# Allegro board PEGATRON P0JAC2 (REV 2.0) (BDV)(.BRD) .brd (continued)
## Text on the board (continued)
Ref Des/Silkscreen Bottom: JP8205 | JP8301 | CON7305 | JP8206 | CON8001 | JP8207 | JP1602 | JP8203 | JP8204 | JP8102 | CON2101 | CON3301 | CON5101 | CON2003 | CON8902 | CON1102 | JP8305 | JP1601 | JP9000 | JP9001 | JP8302 | JP8201 | JP8303 | JP8202 | JP8304 | CON2002 | JP8402 | JP8800 | JP8900 | JP8901 | JP8306 | JP8307 | JP8100 | JP8101 | CON0700 | CON3800 | MAIN | AUX | BOT | 2nd
TOP: list("[Spacing] TOP" "8.Shape to Route Keepout" "0 MIL [DEFAULT]" "0 MIL" "0.00 MIL" "DRC ERROR CLASS/TOP" "[Shape] Route Keepout/Top ((-271.91 4409.28) (9.9 4687.15))" "[Top Shape] GND ((-679.11 -19.37) (3281.09 4854.01))" list(-261.910000 4409.280000) nil)@@@list("bobo_dong" "2014/01/13 20:45:47" nil "S0DCOA89102" "g1t-p0jac.11")@@@nil | list("[Spacing] TOP" "1.Shape to Route Keepin" "0 MIL [DEFAULT]" "0 MIL" "0.00 MIL" "DRC ERROR CLASS/TOP" "[Shape] Route Keepin/All ((-679.03 -19.38) (3281.17 4854.0))" "[Top Shape] GND ((-679.11 -19.37) (3281.09 4854.01))" list(-19.380000 -0.010000) nil)@@@list("bobo_dong" "2014/02/26 15:13:02" nil "S0DCOA89102" "g1t-p0jac.11")@@@list("vincent_kuo" "2014/02/26 12:02:35" nil "VINCENT_KUO-PC" "g1t-p0jac_byt-t.14") | list("[Spacing] TOP" "3.Shape to Route Keepout" "0 MIL [DEFAULT]" "0 MIL" "0.00 MIL" "DRC ERROR CLASS/TOP" "[Shape] Route Keepout/Top ((137.73 235.97) (253.73 351.97))" "[Top Shape] GND ((-679.11 -19.37) (3281.09 4854.01))" list(253.730000 293.970000) nil)@@@list("bobo_dong" "2014/01/13 20:45:44" nil "S0DCOA89102" "g1t-p0jac.11")@@@nil | list("[Spacing] TOP" "9.Thru Via to Route Keepout" "0 MIL [DEFAULT]" "0 MIL" "0.00 MIL" "DRC ERROR CLASS/TOP" "[Shape] Route Keepout/All ((-570.0 2225.0) (410.0 2765.0))" "[ThruVia] AU_HP_L (VIA20D10A32) (340.8 2717.6)" list(350.000000 2721.520000) nil)@@@list("bobo_dong" "2014/01/13 20:45:50" nil "S0DCOA89102" "g1t-p0jac.11")@@@nil | list("[Spacing] TOP" "7.Shape to Route Keepout" "0 MIL [DEFAULT]" "0 MIL" "0.00 MIL" "DRC ERROR CLASS/TOP" "[Shape] Route Keepout/Top ((351.73 4301.97) (467.73 4417.97))" "[Top Shape] GND ((-679.11 -19.37) (3281.09 4854.01))" list(467.730000 4359.970000) nil)@@@list("bobo_dong" "2014/01/13 20:45:47" nil "S0DCOA89102" "g1t-p0jac.11")@@@nil | list("[Spacing] TOP" "2.Shape to Route Keepout" "0 MIL [DEFAULT]" "0 MIL" "0.00 MIL" "DRC ERROR CLASS/TOP" "[Shape] Route Keepout/Top ((2572.73 10.97) (2688.73 126.97))" "[Top Shape] GND ((-679.11 -19.37) (3281.09 4854.01))" list(2688.730000 68.970000) nil)@@@list("bobo_dong" "2014/01/13 20:45:43" nil "S0DCOA89102" "g1t-p0jac.11")@@@nil | list("[Spacing] TOP" "6.Shape to Route Keepout" "0 MIL [DEFAULT]" "0 MIL" "0.00 MIL" "DRC ERROR CLASS/TOP" "[Shape] Route Keepout/Top ((2877.7 3995.9) (3056.0 4292.67))" "[Top Shape] GND ((-679.11 -19.37) (3281.09 4854.01))" list(2887.700000 3995.900000) nil)@@@list("bobo_dong" "2014/01/13 20:45:46" nil "S0DCOA89102" "g1t-p0jac.11")@@@nil | list("[Spacing] TOP" "70.Shape to Route Keepin" "0 MIL [DEFAULT]" "0 MIL" "0.00 MIL" "DRC ERROR CLASS/TOP" "[Shape] Route Keepin/All ((-679.11 -19.37) (3281.09 4854.01))" "[Top Shape] GND ((-679.11 -19.37) (3281.09 4854.01))" list(3104.240000 2379.050000) nil)@@@list("bobo_dong" "2014/01/13 20:45:44" nil "S0DCOA89102" "g1t-p0jac.11")@@@list("vincent_kuo" "2014/01/13 22:08:13" nil "VINCENT_KUO-PC" "g1t-p0jac_byt-t.11") | list("[Spacing] TOP" "1.Shape to Route Keepin" "0 MIL [DEFAULT]" "0 MIL" "0.00 MIL" "DRC ERROR CLASS/TOP" "[Shape] Route Keepin/All ((-679.11 -19.37) (3281.09 4854.01))" "[Top Shape] GND ((2887.7 4005.9) (3163.29 4282.67))" list(3143.290000 4196.060000) nil)@@@list("bobo_dong" "2014/01/13 20:45:41" nil "S0DCOA89102" "g1t-p0jac.11")@@@nil | list("[Spacing] TOP" "1.Shape to Route Keepin" "0 MIL [DEFAULT]" "0 MIL" "0.00 MIL" "DRC ERROR CLASS/TOP" "[Shape] Route Keepin/All ((-679.11 -19.37) (3281.09 4854.01))" "[Top Shape] GND ((-679.11 -19.37) (3281.09 4854.01))" list(3173.920000 1359.560000) nil)@@@list("bobo_dong" "2014/02/25 09:07:14" nil "s0dcoa89102" "g1t-p0jac.11")@@@nil | list("[Spacing] TOP" "1.Shape to Route Keepin" "0 MIL [DEFAULT]" "0 MIL" "0.00 MIL" "DRC ERROR CLASS/TOP" "[Shape] Route Keepin/All ((-679.11 -19.37) (3281.09 4854.01))" "[Top Shape] GND ((-679.11 -19.37) (3281.09 4854.01))" list(3189.060000 1979.830000) nil)@@@list("vincent_kuo" "2014/01/15 11:14:32" nil "VINCENT_KUO-PC" "g1t-p0jac_byt-t.12")@@@list("doris_chen" "2014/01/16 14:58:51" nil "JULIA_YU-PC1" "g1t-p0jac_byt-t.13-chk") | list("[Spacing] TOP" "5.Shape to Route Keepout" "0 MIL [DEFAULT]" "0 MIL" "0.00 MIL" "DRC ERROR CLASS/TOP" "[Shape] Route Keepout/All ((3220.45 3611.18) (3297.22 3837.56))" "[Top Shape] GND ((-679.11 -19.37) (3281.09 4854.01))" list(3281.090000 3837.560000) nil)@@@list("bobo_dong" "2014/01/13 20:45:45" nil "S0DCOA89102" "g1t-p0jac.11")@@@nil | list("[Spacing] TOP" "13.Line to Route Keepout" "0 MIL [DEFAULT]" "0 MIL" "0.00 MIL" "DRC ERROR CLASS/TOP" "[Shape] Route Keepout/Top ((-2910.16 444.47) (-2652.15 1060.2))" "[Line] 50_2.4G_5 ((-2888.16 774.8) (-2835.0 785.8))" list(-2843.860000 780.300000) nil)@@@list("lei_pang" "2013/05/31 11:02:39" nil "TERESA_YU-PC" "15t_ns_mb.100")@@@nil | list("[Spacing] TOP" "12.Line to Route Keepout" "0 MIL [DEFAULT]" "0 MIL" "0.00 MIL" "DRC ERROR CLASS/TOP" "[Shape] Route Keepout/Top ((-2910.16 444.47) (-2652.15 1060.2))" "[Line] 50_2.4G_5 ((-2846.0 774.8) (-2805.6 785.8))" list(-2833.600000 780.300000) nil)@@@list("lei_pang" "2013/05/31 11:02:38" nil "TERESA_YU-PC" "15t_ns_mb.100")@@@nil | list("[Spacing] TOP" "19.Line to Route Keepout" "0 MIL [DEFAULT]" "0 MIL" "0.00 MIL" "DRC ERROR CLASS/TOP" "[Shape] Route Keepout/Top ((-2910.16 444.47) (-2652.15 1060.2))" "[Line] 50_2.4G_0 ((-2768.35 466.47) (-2757.35 666.09))" list(-2762.850000 566.280000) nil)@@@list("lei_pang" "2013/05/31 11:02:45" nil "TERESA_YU-PC" "15t_ns_mb.100")@@@nil | list("[Spacing] TOP" "6.Line to Route Keepout" "0 MIL [DEFAULT]" "0 MIL" "0.00 MIL" "DRC ERROR CLASS/TOP" "[Shape] Route Keepout/Top ((-2910.16 444.47) (-2652.15 1060.2))" "[Line] 50_2.4G_4 ((-2783.6 774.8) (-2737.0 785.8))" list(-2760.300000 780.300000) nil)@@@list("lei_pang" "2013/05/31 11:02:31" nil "TERESA_YU-PC" "15t_ns_mb.100")@@@nil | list("[Spacing] TOP" "18.Line to Route Keepout" "0 MIL [DEFAULT]" "0 MIL" "0.00 MIL" "DRC ERROR CLASS/TOP" "[Shape] Route Keepout/Top ((-2910.16 444.47) (-2652.15 1060.2))" "[Arc] 50_2.4G_0 (-2737.839 660.59)" list(-2759.880000 672.400000) nil)@@@list("lei_pang" "2013/05/31 11:02:44" nil "TERESA_YU-PC" "15t_ns_mb.100")@@@nil | list("[Spacing] TOP" "7.Line to Route Keepout" "0 MIL [DEFAULT]" "0 MIL" "0.00 MIL" "DRC ERROR CLASS/TOP" "[Shape] Route Keepout/Top ((-2910.16 444.47) (-2652.15 1060.2))" "[Line] 50_2.4G_4 ((-2748.0 774.8) (-2707.15 785.8))" list(-2719.890000 780.300000) nil)@@@list("lei_pang" "2013/05/31 11:02:32" nil "TERESA_YU-PC" "15t_ns_mb.100")@@@nil | list("[Spacing] TOP" "17.Line to Route Keepout" "0 MIL [DEFAULT]" "0 MIL" "0.00 MIL" "DRC ERROR CLASS/TOP" "[Shape] Route Keepout/Top ((-2910.16 444.47) (-2652.15 1060.2))" "[Line] 50_2.4G_0 ((-2761.03 672.77) (-2681.47 752.33))" list(-2700.440000 733.360000) nil)@@@list("lei_pang" "2013/05/31 11:02:43" nil "TERESA_YU-PC" "15t_ns_mb.100")@@@nil | list("[Spacing] TOP" "16.Line to Route Keepout" "0 MIL [DEFAULT]" "0 MIL" "0.00 MIL" "DRC ERROR CLASS/TOP" "[Shape] Route Keepout/Top ((-2910.16 444.47) (-2652.15 1060.2))" "[Arc] 50_2.4G_0 (-2704.661 764.51)" list(-2682.620000 752.700000) nil)@@@list("lei_pang" "2013/05/31 11:02:42" nil "TERESA_YU-PC" "15t_ns_mb.100")@@@nil | list("[Spacing] TOP" "10.Line to Route Keepout" "0 MIL [DEFAULT]" "0 MIL" "0.00 MIL" "DRC ERROR CLASS/TOP" "[Shape] Route Keepout/Top ((-2910.16 444.47) (-2652.15 1060.2))" "[Line] 50_2.4G_3 ((-2685.15 996.32) (-2674.15 1038.2))" list(-2679.650000 1026.160000) nil)@@@list("lei_pang" "2013/05/31 11:02:35" nil "TERESA_YU-PC" "15t_ns_mb.100")@@@nil | list("[Spacing] TOP" "9.Line to Route Keepout" "0 MIL [DEFAULT]" "0 MIL" "0.00 MIL" "DRC ERROR CLASS/TOP" "[Shape] Route Keepout/Top ((-2910.16 444.47) (-2652.15 1060.2))" "[Line] 50_2.4G_2 ((-2685.15 932.82) (-2674.15 974.32))" list(-2679.650000 953.570000) nil)@@@list("lei_pang" "2013/05/31 11:02:34" nil "TERESA_YU-PC" "15t_ns_mb.100")@@@nil | list("[Spacing] TOP" "8.Line to Route Keepout" "0 MIL [DEFAULT]" "0 MIL" "0.00 MIL" "DRC ERROR CLASS/TOP" "[Shape] Route Keepout/Top ((-2910.16 444.47) (-2652.15 1060.2))" "[Line] 50_2.4G_2 ((-2685.15 899.42) (-2674.15 943.82))" list(-2679.650000 921.620000) nil)@@@list("lei_pang" "2013/05/31 11:02:33" nil "TERESA_YU-PC" "15t_ns_mb.100")@@@nil | list("[Spacing] TOP" "11.Line to Route Keepout" "0 MIL [DEFAULT]" "0 MIL" "0.00 MIL" "DRC ERROR CLASS/TOP" "[Shape] Route Keepout/Top ((-2910.16 444.47) (-2652.15 1060.2))" "[Line] 50_2.4G_1 ((-2685.15 836.62) (-2674.15 877.42))" list(-2679.650000 857.020000) nil)@@@list("lei_pang" "2013/05/31 11:02:36" nil "TERESA_YU-PC" "15t_ns_mb.100")@@@nil | list("[Spacing] TOP" "15.Line to Route Keepout" "0 MIL [DEFAULT]" "0 MIL" "0.00 MIL" "DRC ERROR CLASS/TOP" "[Shape] Route Keepout/Top ((-2910.16 444.47) (-2652.15 1060.2))" "[Line] 50_2.4G_0 ((-2685.15 774.8) (-2674.15 814.62))" list(-2679.650000 807.800000) nil)@@@list("lei_pang" "2013/05/31 11:02:41" nil "TERESA_YU-PC" "15t_ns_mb.100")@@@nil | list("[Spacing] TOP" "14.Line to Route Keepout" "0 MIL [DEFAULT]" "0 MIL" "0.00 MIL" "DRC ERROR CLASS/TOP" "[Shape] Route Keepout/Top ((-2910.16 444.47) (-2652.15 1060.2))" "[Line] 50_2.4G_0 ((-2685.15 759.01) (-2674.15 785.8))" list(-2679.650000 772.400000) nil)@@@list("lei_pang" "2013/05/31 11:02:40" nil "TERESA_YU-PC" "15t_ns_mb.100")@@@nil | list("[Spacing] TOP" "5.Shape to Route Keepout" "0 MIL [DEFAULT]" "0 MIL" "0.00 MIL" "DRC ERROR CLASS/TOP" "[Shape] Route Keepout/Top ((-2910.16 444.47) (-2652.15 1060.2))" "[Top Shape] 50_2.4G_3 ((-2684.45 891.05) (-2343.04 1048.55))" list(-2652.150000 1022.820000) nil)@@@list("lei_pang" "2013/05/31 11:02:30" nil "TERESA_YU-PC" "15t_ns_mb.100")@@@nil | list("[Spacing] TOP" "10.Thru Via to Route Keepin" "0 MIL [DEFAULT]" "1689.77 MIL" "-1689.77 MIL" "DRC ERROR CLASS/TOP" "[Shape] Route Keepin/All ((-2611.73 -1560.75) (2448.51 1842.01))" "[ThruVia] Dummy (VIA20D10A32) (-2910.0 -2405.0)" list(-2599.980000 -733.740000) nil)@@@list("sky_zheng" "2013/09/13 10:56:13" nil "RDD_704_PC" "g1t-oxygen.10")@@@list("andy_lien" "2013/09/13 12:14:47" nil "ANDY_LIEN-PC" "g1t-oxygen.10") | list("[Spacing] TOP" "9.Thru Via to Route Keepin" "0 MIL [DEFAULT]" "1713.38 MIL" "-1713.38 MIL" "DRC ERROR CLASS/TOP" "[Shape] Route Keepin/All ((-2611.73 -1560.75) (2448.51 1842.01))" "[ThruVia] Dummy (VIA20D10A32) (-2910.0 -2429.0)" list(-2599.940000 -733.750000) nil)@@@list("sky_zheng" "2013/09/13 10:56:14" nil "RDD_704_PC" "g1t-oxygen.10")@@@list("andy_lien" "2013/09/13 12:14:46" nil "ANDY_LIEN-PC" "g1t-oxygen.10") | list("[Spacing] TOP" "5.Shape to Route Keepout" "0 MIL [DEFAULT]" "0 MIL" "0.00 MIL" "DRC ERROR CLASS/TOP" "[Shape] Route Keepout/Top ((-2646.73 1357.01) (-2410.2 1826.97))" "[Top Shape] GND ((-2611.72 -1560.74) (2459.91 1842.0))" list(-2513.290000 1357.010000) nil)@@@list("sky_zheng" "2013/09/13 11:30:03" nil "RDD_704_PC" "g1t-oxygen.10")@@@list("andy_lien" "2013/09/13 12:14:37" nil "ANDY_LIEN-PC" "g1t-oxygen.10") | list("[Spacing] TOP" "4.Shape to Route Keepout" "0 MIL [DEFAULT]" "0 MIL" "0.00 MIL" "DRC ERROR CLASS/TOP" "[Shape] Route Keepout/Top ((-2636.95 -749.36) (-2419.97 -532.38))" "[Top Shape] GND ((-2611.72 -1560.74) (2459.91 1842.0))" list(-2419.970000 -640.370000) nil)@@@list("sky_zheng" "2013/09/13 11:30:02" nil "RDD_704_PC" "g1t-oxygen.10")@@@list("andy_lien" "2013/09/13 12:14:36" nil "ANDY_LIEN-PC" "g1t-oxygen.10") | list("[Spacing-SameNet] TOP" "31.Line to Line Same Net" "3 MIL [DEFAULT]" "0 MIL" "3.00 MIL" "DRC ERROR CLASS/TOP" "[Line] WLBT_3V3 ((-2299.11 137.5) (-2257.99 178.62))" "[Line] WLBT_3V3 ((-2290.11 78.8) (-2258.11 141.5))" list(-2273.990000 153.500000) nil)@@@list("lei_pang" "2013/05/31 11:03:01" nil "TERESA_YU-PC" "15t_ns_mb.100")@@@nil | list("[Spacing] TOP" "8.Line to Route Keepin" "0 MIL [DEFAULT]" "0 MIL" "0.00 MIL" "DRC ERROR CLASS/TOP" "[Shape] Route Keepin/All ((-2611.73 -1560.75) (2448.51 1842.01))" "[Line] PLUGDET_CONN_FB ((-1892.17 1479.03) (-1862.9 1508.3))" list(-1863.500000 1485.130000) nil)@@@list("sky_zheng" "2013/09/13 10:56:05" nil "RDD_704_PC" "g1t-oxygen.10")@@@list("andy_lien" "2013/09/13 12:14:44" nil "ANDY_LIEN-PC" "g1t-oxygen.10") | list("[Spacing] TOP" "7.SMD Pin to SMD Pin Same Net" "4 MIL [DEFAULT]" "OVERLAP" "" "DRC ERROR CLASS/TOP" "[SmdPin] +V1P0SX (<uTiL>cId1341<uTiL>.1) (-1655.0 -286.5)" "[SmdPin] +V1P0SX (<uTiL>cId885<uTiL>.2) (-1667.0 -285.0)" list(-1665.000000 -295.500000) nil)@@@list("sky_zheng" "2013/09/13 10:56:04" nil "RDD_704_PC" "g1t-oxygen.10")@@@list("andy_lien" "2013/09/13 12:14:43" nil "ANDY_LIEN-PC" "g1t-oxygen.10") | list("[Spacing] TOP" "20.Shape to Thru Via" "6 MIL [DEFAULT]" "2.09 MIL" "3.91 MIL" "DRC ERROR CLASS/TOP" "[ThruVia] 50_GPS_0 (VIA20D10A32) (-1601.0 768.0)" "[Top Shape] GND ((-3101.25 -1388.3) (1528.75 1237.87))" list(-1610.520000 771.050000) nil)@@@list("lei_pang" "2013/05/31 11:02:46" nil "TERESA_YU-PC" "15t_ns_mb.100")@@@nil | list("[Spacing] TOP" "1.Shape to Route Keepin" "0 MIL [DEFAULT]" "0 MIL" "0.00 MIL" "DRC ERROR CLASS/TOP" "[Shape] Route Keepin/All ((-2611.73 -1560.75) (2448.51 1842.01))" "[Top Shape] GND ((-1130.82 1739.05) (-1019.6 1813.85))" list(-1129.140000 1739.050000) nil)@@@list("sky_zheng" "2013/09/13 10:54:43" nil "RDD_704_PC" "g1t-oxygen.10")@@@list("andy_lien" "2013/09/13 12:14:27" nil "ANDY_LIEN-PC" "g1t-oxygen.10") | list("[Spacing] TOP" "6.Shape to Route Keepout" "0 MIL [DEFAULT]" "0 MIL" "0.00 MIL" "DRC ERROR CLASS/TOP" "[Shape] Route Keepout/Top ((2181.95 1490.8) (2398.93 1707.78))" "[Top Shape] GND ((-2611.72 -1560.74) (2459.91 1842.0))" list(2295.230000 1702.670000) nil)@@@list("sky_zheng" "2013/09/13 11:30:04" nil "RDD_704_PC" "g1t-oxygen.10")@@@list("andy_lien" "2013/09/13 12:14:38" nil "ANDY_LIEN-PC" "g1t-oxygen.10") | list("[Spacing] TOP" "2.Shape to Route Keepout" "0 MIL [DEFAULT]" "0 MIL" "0.00 MIL" "DRC ERROR CLASS/TOP" "[Shape] Route Keepout/Top ((2182.01 -965.83) (2483.51 -552.13))" "[Top Shape] GND ((-2611.72 -1560.74) (2459.91 1842.0))" list(2373.700000 -557.130000) nil)@@@list("sky_zheng" "2013/09/13 11:29:59" nil "RDD_704_PC" "g1t-oxygen.10")@@@list("andy_lien" "2013/09/13 12:14:29" nil "ANDY_LIEN-PC" "g1t-oxygen.10") | list("[Spacing] TOP" "3.Shape to Route Keepin" "0 MIL [DEFAULT]" "0 MIL" "0.00 MIL" "DRC ERROR CLASS/TOP" "[Shape] Route Keepin/All ((-2611.73 -1560.75) (2448.51 1842.01))" "[Top Shape] GND ((-2611.72 -1560.74) (2459.91 1842.0))" list(2418.390000 -961.140000) nil)@@@list("sky_zheng" "2013/09/13 11:30:00" nil "RDD_704_PC" "g1t-oxygen.10")@@@list("andy_lien" "2013/09/13 12:14:34" nil "ANDY_LIEN-PC" "g1t-oxygen.10") | list("[Spacing] TOP" "1.Shape to Route Keepout" "0 MIL [DEFAULT]" "0 MIL" "0.00 MIL" "DRC ERROR CLASS/TOP" "[Shape] Route Keepout/All ((-2636.73 -1585.75) (2473.51 1867.01))" "[Top Shape] GND ((-2611.72 -1560.74) (2459.91 1842.0))" list(2459.750000 -950.930000) nil)@@@list("sky_zheng" "2013/09/13 11:29:58" nil "RDD_704_PC" "g1t-oxygen.10")@@@nil
Ref Des/Silkscreen Top: H7906 | H7910 | J3101 | H7907 | CON0901 | H7903 | H7901 | H7911 | CON5201 | PCB MADE IN | P0JAC_BYT-T MAIN BOARD | REV:2.0 | 1.5/550MILS | 2014.03.20 | TOP | P0JAC_BYT-T MAIN BOARD REV:2.0 | 180 DEGREE | 0 DEGREE | 1st
L2-SIG: list("[Spacing] L2-SIG" "2.Shape to Route Keepin" "0 MIL [DEFAULT]" "0 MIL" "0.00 MIL" "DRC ERROR CLASS/L2-SIG" "[Shape] Route Keepin/All ((-679.03 -19.38) (3281.17 4854.0))" "[L2-Sig Shape] GND ((-679.11 -19.37) (3281.09 4854.01))" list(-19.380000 -0.010000) nil)@@@list("bobo_dong" "2014/02/26 15:13:03" nil "S0DCOA89102" "g1t-p0jac.11")@@@list("vincent_kuo" "2014/02/26 12:03:26" nil "VINCENT_KUO-PC" "g1t-p0jac_byt-t.14") | list("[Spacing] L2-SIG" "13.Thru Via to Route Keepout" "0 MIL [DEFAULT]" "0 MIL" "0.00 MIL" "DRC ERROR CLASS/L2-SIG" "[Shape] Route Keepout/All ((-570.0 2225.0) (410.0 2765.0))" "[ThruVia] AU_HP_L (VIA20D10A32) (340.8 2717.6)" list(350.000000 2721.520000) nil)@@@list("bobo_dong" "2014/01/13 20:46:38" nil "S0DCOA89102" "g1t-p0jac.11")@@@nil | list("[Spacing] L2-SIG" "2.Shape to Route Keepin" "0 MIL [DEFAULT]" "0 MIL" "0.00 MIL" "DRC ERROR CLASS/L2-SIG" "[Shape] Route Keepin/All ((-679.11 -19.37) (3281.09 4854.01))" "[L2-Sig Shape] GND ((-679.11 -19.37) (3281.09 4854.01))" list(3081.540000 2036.160000) nil)@@@list("bobo_dong" "2014/02/25 09:08:04" nil "s0dcoa89102" "g1t-p0jac.11")@@@nil | list("[Spacing] L2-SIG" "1.Shape to Route Keepin" "0 MIL [DEFAULT]" "0 MIL" "0.00 MIL" "DRC ERROR CLASS/L2-SIG" "[Shape] Route Keepin/All ((-679.11 -19.37) (3281.09 4854.01))" "[L2-Sig Shape] GND ((-679.11 -19.37) (3281.09 4854.01))" list(3104.240000 2379.050000) nil)@@@list("kelly_lv" "2014/01/14 09:49:14" nil "PC-0005358" "5k-castle.105")@@@list("vincent_kuo" "2014/01/13 22:05:46" nil "VINCENT_KUO-PC" "g1t-p0jac_byt-t.11") | list("[Spacing] L2-SIG" "12.Shape to Route Keepin" "0 MIL [DEFAULT]" "0 MIL" "0.00 MIL" "DRC ERROR CLASS/L2-SIG" "[Shape] Route Keepin/All ((-679.11 -19.37) (3281.09 4854.01))" "[L2-Sig Shape] GND ((-679.11 -19.37) (3281.09 4854.01))" list(3121.440000 1684.960000) nil)@@@list("bobo_dong" "2014/01/13 20:46:36" nil "S0DCOA89102" "g1t-p0jac.11")@@@nil | list("[Spacing] L2-SIG" "2.Shape to Route Keepin" "0 MIL [DEFAULT]" "0 MIL" "0.00 MIL" "DRC ERROR CLASS/L2-SIG" "[Shape] Route Keepin/All ((-679.11 -19.37) (3281.09 4854.01))" "[L2-Sig Shape] GND ((-679.11 -19.37) (3281.09 4854.01))" list(3173.920000 1359.560000) nil)@@@list("vincent_kuo" "2014/01/15 11:14:28" nil "VINCENT_KUO-PC" "g1t-p0jac_byt-t.12")@@@list("doris_chen" "2014/01/16 14:58:52" nil "JULIA_YU-PC1" "g1t-p0jac_byt-t.13-chk") | list("[Spacing] L2-SIG" "11.Shape to Route Keepout" "0 MIL [DEFAULT]" "0 MIL" "0.00 MIL" "DRC ERROR CLASS/L2-SIG" "[Shape] Route Keepout/All ((3220.45 3611.18) (3297.22 3837.56))" "[L2-Sig Shape] GND ((-679.11 -19.37) (3281.09 4854.01))" list(3281.090000 3837.560000) nil)@@@list("bobo_dong" "2014/01/13 20:46:35" nil "S0DCOA89102" "g1t-p0jac.11")@@@nil | list("[Spacing] L2-SIG" "4.Thru Via to Route Keepin" "0 MIL [DEFAULT]" "1689.77 MIL" "-1689.77 MIL" "DRC ERROR CLASS/L2-SIG" "[Shape] Route Keepin/All ((-2611.73 -1560.75) (2448.51 1842.01))" "[ThruVia] Dummy (VIA20D10A32) (-2910.0 -2405.0)" list(-2599.980000 -733.740000) nil)@@@list("sky_zheng" "2013/09/13 10:56:20" nil "RDD_704_PC" "g1t-oxygen.10")@@@list("andy_lien" "2013/09/13 12:14:52" nil "ANDY_LIEN-PC" "g1t-oxygen.10") | list("[Spacing] L2-SIG" "3.Thru Via to Route Keepin" "0 MIL [DEFAULT]" "1713.38 MIL" "-1713.38 MIL" "DRC ERROR CLASS/L2-SIG" "[Shape] Route Keepin/All ((-2611.73 -1560.75) (2448.51 1842.01))" "[ThruVia] Dummy (VIA20D10A32) (-2910.0 -2429.0)" list(-2599.940000 -733.750000) nil)@@@list("sky_zheng" "2013/09/13 10:56:21" nil "RDD_704_PC" "g1t-oxygen.10")@@@list("andy_lien" "2013/09/13 12:14:51" nil "ANDY_LIEN-PC" "g1t-oxygen.10") | list("[Spacing] L2-SIG" "1.Shape to Route Keepin" "0 MIL [DEFAULT]" "0 MIL" "0.00 MIL" "DRC ERROR CLASS/L2-SIG" "[Shape] Route Keepin/All ((-2611.73 -1560.75) (2448.51 1842.01))" "[L2-Sig Shape] GND ((-2199.6 1385.1) (-2005.01 1752.87))" list(-2195.600000 1424.680000) nil)@@@list("sky_zheng" "2013/09/13 10:56:19" nil "RDD_704_PC" "g1t-oxygen.10")@@@list("andy_lien" "2013/09/13 12:14:50" nil "ANDY_LIEN-PC" "g1t-oxygen.10") | list("[Spacing] L2-SIG" "19.Microvia to Route Keepin" "0 MIL [DEFAULT]" "46.46 MIL" "-46.46 MIL" "DRC ERROR CLASS/L2-SIG" "[Shape] Route Keepin/All ((-2611.73 -1560.75) (2448.51 1842.01))" "[B/BVia] Dummy (VIA10D4A24-L2-L3) (-1175.0 1805.0)" list(-1123.540000 1805.000000) nil)@@@list("sky_zheng" "2013/09/13 10:56:22" nil "RDD_704_PC" "g1t-oxygen.10")@@@nil | list("[Spacing] L2-SIG" "21.Microvia to Route Keepin" "0 MIL [DEFAULT]" "46.46 MIL" "-46.46 MIL" "DRC ERROR CLASS/L2-SIG" "[Shape] Route Keepin/All ((-2611.73 -1560.75) (2448.51 1842.01))" "[B/BVia] Dummy (VIA10D4A24-L2-L3) (-1175.0 1790.0)" list(-1123.540000 1790.000000) nil)@@@list("sky_zheng" "2013/09/13 10:56:24" nil "RDD_704_PC" "g1t-oxygen.10")@@@nil | list("[Spacing] L2-SIG" "20.Microvia to Route Keepin" "0 MIL [DEFAULT]" "46.46 MIL" "-46.46 MIL" "DRC ERROR CLASS/L2-SIG" "[Shape] Route Keepin/All ((-2611.73 -1560.75) (2448.51 1842.01))" "[B/BVia] Dummy (VIA10D4A24-L2-L3) (-1175.0 1775.0)" list(-1123.540000 1775.000000) nil)@@@list("sky_zheng" "2013/09/13 10:56:23" nil "RDD_704_PC" "g1t-oxygen.10")@@@nil | list("[Spacing] L2-SIG" "2.Shape to Route Keepin" "0 MIL [DEFAULT]" "0 MIL" "0.00 MIL" "DRC ERROR CLASS/L2-SIG" "[Shape] Route Keepin/All ((-2611.73 -1560.75) (2448.51 1842.01))" "[L2-Sig Shape] GND ((-2611.73 -1560.75) (2448.51 1842.01))" list(-13.300000 -778.660000) nil)@@@list("sky_zheng" "2013/09/13 10:56:18" nil "RDD_704_PC" "g1t-oxygen.10")@@@list("andy_lien" "2013/09/13 12:14:51" nil "ANDY_LIEN-PC" "g1t-oxygen.10") | list("[Spacing] L2-SIG" "13.Shape to Route Keepout" "0 MIL [DEFAULT]" "0 MIL" "0.00 MIL" "DRC ERROR CLASS/L2-SIG" "[Shape] Route Keepout/All ((190.63 -1315.47) (634.34 -438.7))" "[L2-Sig Shape] GND ((170.63 -1335.48) (654.34 -418.71))" list(190.630000 -495.210000) nil)@@@list("sky_zheng" "2013/09/13 10:56:15" nil "RDD_704_PC" "g1t-oxygen.10")@@@nil | list("[Spacing] L2-SIG" "14.Shape to Route Keepout" "0 MIL [DEFAULT]" "0 MIL" "0.00 MIL" "DRC ERROR CLASS/L2-SIG" "[Shape] Route Keepout/All ((184.14 -1363.31) (414.46 -390.87))" "[L2-Sig Shape] GND ((170.63 -1335.48) (654.34 -418.71))" list(390.830000 -418.710000) nil)@@@list("sky_zheng" "2013/09/13 10:56:15" nil "RDD_704_PC" "g1t-oxygen.10")@@@nil
L3-GND: list("[Spacing] L3-GND" "3.Shape to Route Keepin" "0 MIL [DEFAULT]" "0 MIL" "0.00 MIL" "DRC ERROR CLASS/L3-GND" "[Shape] Route Keepin/All ((-679.03 -19.38) (3281.17 4854.0))" "[L3-Gnd Shape] GND ((-679.11 -19.37) (3281.09 4854.01))" list(-19.380000 -0.010000) nil)@@@list("bobo_dong" "2014/02/26 15:13:05" nil "S0DCOA89102" "g1t-p0jac.11")@@@list("vincent_kuo" "2014/02/26 12:03:27" nil "VINCENT_KUO-PC" "g1t-p0jac_byt-t.14") | list("[Spacing] L3-GND" "16.Thru Via to Route Keepout" "0 MIL [DEFAULT]" "0 MIL" "0.00 MIL" "DRC ERROR CLASS/L3-GND" "[Shape] Route Keepout/All ((-570.0 2225.0) (410.0 2765.0))" "[ThruVia] AU_HP_L (VIA20D10A32) (340.8 2717.6)" list(350.000000 2721.520000) nil)@@@list("bobo_dong" "2014/01/13 20:46:43" nil "S0DCOA89102" "g1t-p0jac.11")@@@nil | list("[Spacing] L3-GND" "15.BB Via to Route Keepout" "0 MIL [DEFAULT]" "0 MIL" "0.00 MIL" "DRC ERROR CLASS/L3-GND" "[Shape] Route Keepout/All ((155.0 2225.0) (480.0 2457.5))" "[B/BVia] MICBIAS1 (VIA18D8A26-L3-L6) (413.0 2410.0)" list(420.000000 2415.660000) nil)@@@list("bobo_dong" "2014/01/13 20:46:41" nil "S0DCOA89102" "g1t-p0jac.11")@@@nil | list("[Spacing] L3-GND" "4.Shape to Route Keepin" "0 MIL [DEFAULT]" "0 MIL" "0.00 MIL" "DRC ERROR CLASS/L3-GND" "[Shape] Route Keepin/All ((-679.11 -19.37) (3281.09 4854.01))" "[L3-Gnd Shape] GND ((-679.11 -19.37) (3281.09 4854.01))" list(3104.240000 2379.050000) nil)@@@list("bobo_dong" "2014/01/13 20:46:39" nil "S0DCOA89102" "g1t-p0jac.11")@@@list("vincent_kuo" "2014/01/13 22:05:47" nil "VINCENT_KUO-PC" "g1t-p0jac_byt-t.11") | list("[Spacing] L3-GND" "3.Shape to Route Keepin" "0 MIL [DEFAULT]" "0 MIL" "0.00 MIL" "DRC ERROR CLASS/L3-GND" "[Shape] Route Keepin/All ((-679.11 -19.37) (3281.09 4854.01))" "[L3-Gnd Shape] GND ((-679.11 -19.37) (3281.09 4854.01))" list(3173.920000 1359.560000) nil)@@@list("bobo_dong" "2014/01/27 15:50:15" nil "s0dcoa89102" "g1t-p0jac.11")@@@nil | list("[Spacing] L3-GND" "3.Shape to Route Keepin" "0 MIL [DEFAULT]" "0 MIL" "0.00 MIL" "DRC ERROR CLASS/L3-GND" "[Shape] Route Keepin/All ((-679.11 -19.37) (3281.09 4854.01))" "[L3-Gnd Shape] GND ((-679.11 -19.37) (3281.09 4854.01))" list(3189.060000 1979.830000) nil)@@@list("bobo_dong" "2014/01/15 10:38:53" nil "S0DCOA89102" "g1t-p0jac.11")@@@list("doris_chen" "2014/01/16 14:58:53" nil "JULIA_YU-PC1" "g1t-p0jac_byt-t.13-chk") | list("[Spacing] L3-GND" "4.Thru Via to Route Keepin" "0 MIL [DEFAULT]" "1689.77 MIL" "-1689.77 MIL" "DRC ERROR CLASS/L3-GND" "[Shape] Route Keepin/All ((-2611.73 -1560.75) (2448.51 1842.01))" "[ThruVia] Dummy (VIA20D10A32) (-2910.0 -2405.0)" list(-2599.980000 -733.740000) nil)@@@list("sky_zheng" "2013/09/13 10:56:29" nil "RDD_704_PC" "g1t-oxygen.10")@@@list("andy_lien" "2013/09/13 12:14:56" nil "ANDY_LIEN-PC" "g1t-oxygen.10") | list("[Spacing] L3-GND" "3.Thru Via to Route Keepin" "0 MIL [DEFAULT]" "1713.38 MIL" "-1713.38 MIL" "DRC ERROR CLASS/L3-GND" "[Shape] Route Keepin/All ((-2611.73 -1560.75) (2448.51 1842.01))" "[ThruVia] Dummy (VIA20D10A32) (-2910.0 -2429.0)" list(-2599.940000 -733.750000) nil)@@@list("sky_zheng" "2013/09/13 10:56:30" nil "RDD_704_PC" "g1t-oxygen.10")@@@list("andy_lien" "2013/09/13 12:14:55" nil "ANDY_LIEN-PC" "g1t-oxygen.10") | list("[Spacing] L3-GND" "1.BB Via to Route Keepin" "0 MIL [DEFAULT]" "2040.83 MIL" "-2040.83 MIL" "DRC ERROR CLASS/L3-GND" "[Shape] Route Keepin/All ((-2611.73 -1560.75) (2448.51 1842.01))" "[B/BVia] Dummy (VIA18D8A26-L3-L6) (-2910.0 -2760.0)" list(-2599.530000 -733.810000) nil)@@@list("sky_zheng" "2013/09/13 10:56:31" nil "RDD_704_PC" "g1t-oxygen.10")@@@list("andy_lien" "2013/09/13 12:14:55" nil "ANDY_LIEN-PC" "g1t-oxygen.10") | list("[Spacing] L3-GND" "2.BB Via to Route Keepin" "0 MIL [DEFAULT]" "2062.58 MIL" "-2062.58 MIL" "DRC ERROR CLASS/L3-GND" "[Shape] Route Keepin/All ((-2611.73 -1560.75) (2448.51 1842.01))" "[B/BVia] Dummy (VIA18D8A26-L3-L6) (-2910.0 -2782.0)" list(-2599.510000 -733.820000) nil)@@@list("sky_zheng" "2013/09/13 10:56:32" nil "RDD_704_PC" "g1t-oxygen.10")@@@list("andy_lien" "2013/09/13 12:14:55" nil "ANDY_LIEN-PC" "g1t-oxygen.10") | list("[Spacing] L3-GND" "26.Microvia to Route Keepin" "0 MIL [DEFAULT]" "46.46 MIL" "-46.46 MIL" "DRC ERROR CLASS/L3-GND" "[Shape] Route Keepin/All ((-2611.73 -1560.75) (2448.51 1842.01))" "[B/BVia] Dummy (VIA10D4A24-L2-L3) (-1175.0 1805.0)" list(-1123.540000 1805.000000) nil)@@@list("sky_zheng" "2013/09/13 10:56:33" nil "RDD_704_PC" "g1t-oxygen.10")@@@nil | list("[Spacing] L3-GND" "28.Microvia to Route Keepin" "0 MIL [DEFAULT]" "46.46 MIL" "-46.46 MIL" "DRC ERROR CLASS/L3-GND" "[Shape] Route Keepin/All ((-2611.73 -1560.75) (2448.51 1842.01))" "[B/BVia] Dummy (VIA10D4A24-L2-L3) (-1175.0 1790.0)" list(-1123.540000 1790.000000) nil)@@@list("sky_zheng" "2013/09/13 10:56:53" nil "RDD_704_PC" "g1t-oxygen.10")@@@nil | list("[Spacing] L3-GND" "27.Microvia to Route Keepin" "0 MIL [DEFAULT]" "46.46 MIL" "-46.46 MIL" "DRC ERROR CLASS/L3-GND" "[Shape] Route Keepin/All ((-2611.73 -1560.75) (2448.51 1842.01))" "[B/BVia] Dummy (VIA10D4A24-L2-L3) (-1175.0 1775.0)" list(-1123.540000 1775.000000) nil)@@@list("sky_zheng" "2013/09/13 10:56:34" nil "RDD_704_PC" "g1t-oxygen.10")@@@nil
L4-SIG: list("[Spacing] L4-SIG" "4.Shape to Route Keepin" "0 MIL [DEFAULT]" "0 MIL" "0.00 MIL" "DRC ERROR CLASS/L4-SIG" "[Shape] Route Keepin/All ((-679.03 -19.38) (3281.17 4854.0))" "[L4-Sig Shape] GND ((-679.11 -19.37) (3281.09 4854.01))" list(-19.380000 -0.010000) nil)@@@list("bobo_dong" "2014/02/26 15:13:15" nil "S0DCOA89102" "g1t-p0jac.11")@@@list("vincent_kuo" "2014/02/26 12:03:29" nil "VINCENT_KUO-PC" "g1t-p0jac_byt-t.14") | list("[Spacing] L4-SIG" "25.Line to Route Keepout" "0 MIL [DEFAULT]" "0 MIL" "0.00 MIL" "DRC ERROR CLASS/L4-SIG" "[Shape] Route Keepout/All ((-570.0 2225.0) (410.0 2765.0))" "[Line] +V1P8S ((126.33 2508.0) (465.74 2518.0))" list(275.000000 2513.000000) nil)@@@list("bobo_dong" "2014/01/13 20:46:53" nil "S0DCOA89102" "g1t-p0jac.11")@@@nil | list("[Spacing] L4-SIG" "20.Thru Via to Route Keepout" "0 MIL [DEFAULT]" "0 MIL" "0.00 MIL" "DRC ERROR CLASS/L4-SIG" "[Shape] Route Keepout/All ((-570.0 2225.0) (410.0 2765.0))" "[ThruVia] AU_HP_L (VIA20D10A32) (340.8 2717.6)" list(350.000000 2721.520000) nil)@@@list("bobo_dong" "2014/01/13 20:46:48" nil "S0DCOA89102" "g1t-p0jac.11")@@@nil | list("[Spacing] L4-SIG" "1.Line to Route Keepout" "0 MIL [DEFAULT]" "0 MIL" "0.00 MIL" "DRC ERROR CLASS/L4-SIG" "[Shape] Route Keepout/All ((155.0 2225.0) (480.0 2457.5))" "[Line] GND ((195.8 2054.8) (386.0 2245.0))" list(366.000000 2225.000000) nil)@@@list("bobo_dong" "2014/01/13 21:08:35" nil "S0DCOA89102" "g1t-p0jac.11")@@@nil | list("[Spacing] L4-SIG" "24.Line to Route Keepout" "0 MIL [DEFAULT]" "0 MIL" "0.00 MIL" "DRC ERROR CLASS/L4-SIG" "[Shape] Route Keepout/All ((155.0 2225.0) (480.0 2457.5))" "[Line] GND ((195.8 2054.8) (391.2 2250.2))" list(366.000000 2225.000000) nil)@@@list("bobo_dong" "2014/01/13 20:46:52" nil "S0DCOA89102" "g1t-p0jac.11")@@@nil | list("[Spacing] L4-SIG" "2.Line to Route Keepout" "0 MIL [DEFAULT]" "0 MIL" "0.00 MIL" "DRC ERROR CLASS/L4-SIG" "[Shape] Route Keepout/All ((155.0 2225.0) (480.0 2457.5))" "[Line] GND ((366.0 2225.0) (452.2 2245.0))" list(409.100000 2235.000000) nil)@@@list("bobo_dong" "2014/01/13 21:08:36" nil "S0DCOA89102" "g1t-p0jac.11")@@@nil | list("[Spacing] L4-SIG" "22.Line to Route Keepout" "0 MIL [DEFAULT]" "0 MIL" "0.00 MIL" "DRC ERROR CLASS/L4-SIG" "[Shape] Route Keepout/All ((155.0 2225.0) (480.0 2457.5))" "[Line] GND ((371.2 2230.2) (457.4 2250.2))" list(414.300000 2240.200000) nil)@@@list("bobo_dong" "2014/01/13 20:46:50" nil "S0DCOA89102" "g1t-p0jac.11")@@@nil | list("[Spacing] L4-SIG" "19.BB Via to Route Keepout" "0 MIL [DEFAULT]" "0 MIL" "0.00 MIL" "DRC ERROR CLASS/L4-SIG" "[Shape] Route Keepout/All ((155.0 2225.0) (480.0 2457.5))" "[B/BVia] MICBIAS1 (VIA18D8A26-L3-L6) (413.0 2410.0)" list(420.000000 2415.660000) nil)@@@list("bobo_dong" "2014/01/13 20:46:47" nil "S0DCOA89102" "g1t-p0jac.11")@@@nil | list("[Spacing] L4-SIG" "21.Line to Route Keepout" "0 MIL [DEFAULT]" "0 MIL" "0.00 MIL" "DRC ERROR CLASS/L4-SIG" "[Shape] Route Keepout/All ((155.0 2225.0) (480.0 2457.5))" "[Line] GND ((437.4 2230.2) (475.23 2268.03))" list(452.200000 2245.000000) nil)@@@list("bobo_dong" "2014/01/13 20:46:50" nil "S0DCOA89102" "g1t-p0jac.11")@@@nil | list("[Spacing] L4-SIG" "3.Line to Route Keepout" "0 MIL [DEFAULT]" "0 MIL" "0.00 MIL" "DRC ERROR CLASS/L4-SIG" "[Shape] Route Keepout/All ((155.0 2225.0) (480.0 2457.5))" "[Line] GND ((432.2 2225.0) (475.23 2268.03))" list(452.200000 2245.000000) nil)@@@list("bobo_dong" "2014/01/13 21:08:37" nil "S0DCOA89102" "g1t-p0jac.11")@@@nil | list("[Spacing] L4-SIG" "23.Line to Route Keepout" "0 MIL [DEFAULT]" "0 MIL" "0.00 MIL" "DRC ERROR CLASS/L4-SIG" "[Shape] Route Keepout/All ((155.0 2225.0) (480.0 2457.5))" "[Line] GND ((455.23 2248.03) (475.23 2479.48))" list(465.230000 2378.910000) nil)@@@list("bobo_dong" "2014/01/13 20:46:51" nil "S0DCOA89102" "g1t-p0jac.11")@@@nil | list("[Spacing] L4-SIG" "3.Shape to Route Keepin" "0 MIL [DEFAULT]" "0 MIL" "0.00 MIL" "DRC ERROR CLASS/L4-SIG" "[Shape] Route Keepin/All ((-679.11 -19.37) (3281.09 4854.01))" "[L4-Sig Shape] GND ((-679.11 -19.37) (3281.09 4854.01))" list(3080.680000 2370.190000) nil)@@@list("bobo_dong" "2014/02/25 09:08:09" nil "s0dcoa89102" "g1t-p0jac.11")@@@list("vincent_kuo" "2014/01/13 22:05:48" nil "VINCENT_KUO-PC" "g1t-p0jac_byt-t.11") | list("[Spacing] L4-SIG" "4.Shape to Route Keepin" "0 MIL [DEFAULT]" "0 MIL" "0.00 MIL" "DRC ERROR CLASS/L4-SIG" "[Shape] Route Keepin/All ((-679.11 -19.37) (3281.09 4854.01))" "[L4-Sig Shape] GND ((-679.11 -19.37) (3281.09 4854.01))" list(3173.920000 1359.560000) nil)@@@list("vincent_kuo" "2014/01/15 11:14:29" nil "VINCENT_KUO-PC" "g1t-p0jac_byt-t.12")@@@list("doris_chen" "2014/01/16 14:58:55" nil "JULIA_YU-PC1" "g1t-p0jac_byt-t.13-chk") | list("[Spacing] L4-SIG" "17.Shape to Route Keepout" "0 MIL [DEFAULT]" "0 MIL" "0.00 MIL" "DRC ERROR CLASS/L4-SIG" "[Shape] Route Keepout/All ((3220.45 3611.18) (3297.22 3837.56))" "[L4-Sig Shape] GND ((-679.11 -19.37) (3281.09 4854.01))" list(3281.090000 3837.560000) nil)@@@list("bobo_dong" "2014/01/13 20:46:44" nil "S0DCOA89102" "g1t-p0jac.11")@@@nil | list("[Spacing] L4-SIG" "6.Thru Via to Route Keepin" "0 MIL [DEFAULT]" "1689.77 MIL" "-1689.77 MIL" "DRC ERROR CLASS/L4-SIG" "[Shape] Route Keepin/All ((-2611.73 -1560.75) (2448.51 1842.01))" "[ThruVia] Dummy (VIA20D10A32) (-2910.0 -2405.0)" list(-2599.980000 -733.740000) nil)@@@list("sky_zheng" "2013/09/13 10:56:58" nil "RDD_704_PC" "g1t-oxygen.10")@@@list("andy_lien" "2013/09/13 12:15:01" nil "ANDY_LIEN-PC" "g1t-oxygen.10") | list("[Spacing] L4-SIG" "5.Thru Via to Route Keepin" "0 MIL [DEFAULT]" "1713.38 MIL" "-1713.38 MIL" "DRC ERROR CLASS/L4-SIG" "[Shape] Route Keepin/All ((-2611.73 -1560.75) (2448.51 1842.01))" "[ThruVia] Dummy (VIA20D10A32) (-2910.0 -2429.0)" list(-2599.940000 -733.750000) nil)@@@list("sky_zheng" "2013/09/13 10:56:59" nil "RDD_704_PC" "g1t-oxygen.10")@@@list("andy_lien" "2013/09/13 12:15:00" nil "ANDY_LIEN-PC" "g1t-oxygen.10") | list("[Spacing] L4-SIG" "3.BB Via to Route Keepin" "0 MIL [DEFAULT]" "2040.83 MIL" "-2040.83 MIL" "DRC ERROR CLASS/L4-SIG" "[Shape] Route Keepin/All ((-2611.73 -1560.75) (2448.51 1842.01))" "[B/BVia] Dummy (VIA18D8A26-L3-L6) (-2910.0 -2760.0)" list(-2599.530000 -733.810000) nil)@@@list("sky_zheng" "2013/09/13 10:57:00" nil "RDD_704_PC" "g1t-oxygen.10")@@@list("andy_lien" "2013/09/13 12:14:59" nil "ANDY_LIEN-PC" "g1t-oxygen.10") | list("[Spacing] L4-SIG" "4.BB Via to Route Keepin" "0 MIL [DEFAULT]" "2062.58 MIL" "-2062.58 MIL" "DRC ERROR CLASS/L4-SIG" "[Shape] Route Keepin/All ((-2611.73 -1560.75) (2448.51 1842.01))" "[B/BVia] Dummy (VIA18D8A26-L3-L6) (-2910.0 -2782.0)" list(-2599.510000 -733.820000) nil)@@@list("sky_zheng" "2013/09/13 10:57:01" nil "RDD_704_PC" "g1t-oxygen.10")@@@list("andy_lien" "2013/09/13 12:15:00" nil "ANDY_LIEN-PC" "g1t-oxygen.10") | list("[Spacing] L4-SIG" "1.Shape to Route Keepin" "0 MIL [DEFAULT]" "0 MIL" "0.00 MIL" "DRC ERROR CLASS/L4-SIG" "[Shape] Route Keepin/All ((-2611.73 -1560.75) (2448.51 1842.01))" "[L4-Sig Shape] GND ((-2199.6 1385.1) (-2005.01 1752.87))" list(-2195.600000 1424.680000) nil)@@@list("sky_zheng" "2013/09/13 10:56:56" nil "RDD_704_PC" "g1t-oxygen.10")@@@list("andy_lien" "2013/09/13 12:14:58" nil "ANDY_LIEN-PC" "g1t-oxygen.10") | list("[Spacing] L4-SIG" "2.Shape to Route Keepin" "0 MIL [DEFAULT]" "0 MIL" "0.00 MIL" "DRC ERROR CLASS/L4-SIG" "[Shape] Route Keepin/All ((-2611.73 -1560.75) (2448.51 1842.01))" "[L4-Sig Shape] GND ((-2611.73 -1560.75) (2448.51 1842.01))" list(-13.300000 -778.660000) nil)@@@list("sky_zheng" "2013/09/13 10:56:57" nil "RDD_704_PC" "g1t-oxygen.10")@@@list("andy_lien" "2013/09/13 12:14:59" nil "ANDY_LIEN-PC" "g1t-oxygen.10") | list("[Spacing] L4-SIG" "29.Shape to Route Keepout" "0 MIL [DEFAULT]" "0 MIL" "0.00 MIL" "DRC ERROR CLASS/L4-SIG" "[Shape] Route Keepout/All ((190.63 -1315.47) (634.34 -438.7))" "[L4-Sig Shape] GND ((170.63 -1335.48) (654.34 -418.71))" list(190.630000 -495.210000) nil)@@@list("sky_zheng" "2013/09/13 10:56:55" nil "RDD_704_PC" "g1t-oxygen.10")@@@nil | list("[Spacing] L4-SIG" "30.Shape to Route Keepout" "0 MIL [DEFAULT]" "0 MIL" "0.00 MIL" "DRC ERROR CLASS/L4-SIG" "[Shape] Route Keepout/All ((184.14 -1363.31) (414.46 -390.87))" "[L4-Sig Shape] GND ((170.63 -1335.48) (654.34 -418.71))" list(390.830000 -418.710000) nil)@@@list("sky_zheng" "2013/09/13 10:56:55" nil "RDD_704_PC" "g1t-oxygen.10")@@@nil
L5-SIG: list("[Spacing] L5-SIG" "5.Shape to Route Keepin" "0 MIL [DEFAULT]" "0 MIL" "0.00 MIL" "DRC ERROR CLASS/L5-SIG" "[Shape] Route Keepin/All ((-679.03 -19.38) (3281.17 4854.0))" "[L5-Sig Shape] GND ((-679.11 -19.37) (3281.09 4854.01))" list(-19.380000 -0.010000) nil)@@@list("bobo_dong" "2014/02/26 15:13:17" nil "S0DCOA89102" "g1t-p0jac.11")@@@list("vincent_kuo" "2014/02/26 12:03:44" nil "VINCENT_KUO-PC" "g1t-p0jac_byt-t.14") | list("[Spacing] L5-SIG" "30.Line to Route Keepout" "0 MIL [DEFAULT]" "0 MIL" "0.00 MIL" "DRC ERROR CLASS/L5-SIG" "[Shape] Route Keepout/All ((-570.0 2225.0) (410.0 2765.0))" "[Line] AU_HP_JD# ((10.6 2449.6) (91.0 2530.0))" list(30.600000 2510.000000) nil)@@@list("bobo_dong" "2014/01/13 20:46:59" nil "S0DCOA89102" "g1t-p0jac.11")@@@nil | list("[Spacing] L5-SIG" "32.Line to Route Keepout" "0 MIL [DEFAULT]" "0 MIL" "0.00 MIL" "DRC ERROR CLASS/L5-SIG" "[Shape] Route Keepout/All ((-570.0 2225.0) (410.0 2765.0))" "[Line] AU_HP_L ((338.8 2690.08) (342.8 2719.6))" list(340.800000 2692.560000) nil)@@@list("bobo_dong" "2014/01/13 20:47:01" nil "S0DCOA89102" "g1t-p0jac.11")@@@nil | list("[Spacing] L5-SIG" "31.Line to Route Keepout" "0 MIL [DEFAULT]" "0 MIL" "0.00 MIL" "DRC ERROR CLASS/L5-SIG" "[Shape] Route Keepout/All ((-570.0 2225.0) (410.0 2765.0))" "[Line] AU_HP_L ((314.72 2666.0) (342.8 2694.08))" list(340.800000 2692.080000) nil)@@@list("bobo_dong" "2014/01/13 20:47:00" nil "S0DCOA89102" "g1t-p0jac.11")@@@nil | list("[Spacing] L5-SIG" "33.Thru Via to Route Keepout" "0 MIL [DEFAULT]" "0 MIL" "0.00 MIL" "DRC ERROR CLASS/L5-SIG" "[Shape] Route Keepout/All ((-570.0 2225.0) (410.0 2765.0))" "[ThruVia] AU_HP_L (VIA20D10A32) (340.8 2717.6)" list(350.000000 2721.520000) nil)@@@list("bobo_dong" "2014/01/13 20:47:02" nil "S0DCOA89102" "g1t-p0jac.11")@@@nil | list("[Spacing] L5-SIG" "29.BB Via to Route Keepout" "0 MIL [DEFAULT]" "0 MIL" "0.00 MIL" "DRC ERROR CLASS/L5-SIG" "[Shape] Route Keepout/All ((155.0 2225.0) (480.0 2457.5))" "[B/BVia] MICBIAS1 (VIA18D8A26-L3-L6) (413.0 2410.0)" list(420.000000 2415.660000) nil)@@@list("bobo_dong" "2014/01/13 20:46:57" nil "S0DCOA89102" "g1t-p0jac.11")@@@nil | list("[Spacing] L5-SIG" "26.Shape to Route Keepout" "0 MIL [DEFAULT]" "0 MIL" "0.00 MIL" "DRC ERROR CLASS/L5-SIG" "[Shape] Route Keepout/All ((3056.9 2031.81) (3317.13 2375.11))" "[L5-Sig Shape] GND ((-679.11 -19.37) (3281.09 4854.01))" list(3080.340000 2369.890000) nil)@@@list("bobo_dong" "2014/01/13 20:46:54" nil "S0DCOA89102" "g1t-p0jac.11")@@@nil | list("[Spacing] L5-SIG" "4.Shape to Route Keepin" "0 MIL [DEFAULT]" "0 MIL" "0.00 MIL" "DRC ERROR CLASS/L5-SIG" "[Shape] Route Keepin/All ((-679.11 -19.37) (3281.09 4854.01))" "[L5-Sig Shape] GND ((-679.11 -19.37) (3281.09 4854.01))" list(3173.940000 1359.560000) nil)@@@list("bobo_dong" "2014/02/25 09:08:13" nil "s0dcoa89102" "g1t-p0jac.11")@@@list("vincent_kuo" "2014/01/13 22:06:21" nil "VINCENT_KUO-PC" "g1t-p0jac_byt-t.11") | list("[Spacing] L5-SIG" "5.Shape to Route Keepin" "0 MIL [DEFAULT]" "0 MIL" "0.00 MIL" "DRC ERROR CLASS/L5-SIG" "[Shape] Route Keepin/All ((-679.11 -19.37) (3281.09 4854.01))" "[L5-Sig Shape] GND ((-679.11 -19.37) (3281.09 4854.01))" list(3177.480000 2028.030000) nil)@@@list("bobo_dong" "2014/01/15 09:08:39" nil "S0DCOA89102" "g1t-p0jac.11")@@@list("doris_chen" "2014/01/16 14:58:55" nil "JULIA_YU-PC1" "g1t-p0jac_byt-t.13-chk") | list("[Spacing] L5-SIG" "27.Shape to Route Keepout" "0 MIL [DEFAULT]" "0 MIL" "0.00 MIL" "DRC ERROR CLASS/L5-SIG" "[Shape] Route Keepout/All ((3220.45 3611.18) (3297.22 3837.56))" "[L5-Sig Shape] GND ((-679.11 -19.37) (3281.09 4854.01))" list(3281.090000 3837.560000) nil)@@@list("bobo_dong" "2014/01/13 20:46:55" nil "S0DCOA89102" "g1t-p0jac.11")@@@nil | list("[Spacing] L5-SIG" "6.Thru Via to Route Keepin" "0 MIL [DEFAULT]" "1689.77 MIL" "-1689.77 MIL" "DRC ERROR CLASS/L5-SIG" "[Shape] Route Keepin/All ((-2611.73 -1560.75) (2448.51 1842.01))" "[ThruVia] Dummy (VIA20D10A32) (-2910.0 -2405.0)" list(-2599.980000 -733.740000) nil)@@@list("sky_zheng" "2013/09/13 10:57:13" nil "RDD_704_PC" "g1t-oxygen.10")@@@list("andy_lien" "2013/09/13 12:15:09" nil "ANDY_LIEN-PC" "g1t-oxygen.10") | list("[Spacing] L5-SIG" "5.Thru Via to Route Keepin" "0 MIL [DEFAULT]" "1713.38 MIL" "-1713.38 MIL" "DRC ERROR CLASS/L5-SIG" "[Shape] Route Keepin/All ((-2611.73 -1560.75) (2448.51 1842.01))" "[ThruVia] Dummy (VIA20D10A32) (-2910.0 -2429.0)" list(-2599.940000 -733.750000) nil)@@@list("sky_zheng" "2013/09/13 10:57:15" nil "RDD_704_PC" "g1t-oxygen.10")@@@list("andy_lien" "2013/09/13 12:15:08" nil "ANDY_LIEN-PC" "g1t-oxygen.10") | list("[Spacing] L5-SIG" "4.BB Via to Route Keepin" "0 MIL [DEFAULT]" "2040.83 MIL" "-2040.83 MIL" "DRC ERROR CLASS/L5-SIG" "[Shape] Route Keepin/All ((-2611.73 -1560.75) (2448.51 1842.01))" "[B/BVia] Dummy (VIA18D8A26-L3-L6) (-2910.0 -2760.0)" list(-2599.530000 -733.810000) nil)@@@list("sky_zheng" "2013/09/13 10:57:15" nil "RDD_704_PC" "g1t-oxygen.10")@@@list("andy_lien" "2013/09/13 12:15:07" nil "ANDY_LIEN-PC" "g1t-oxygen.10") | list("[Spacing] L5-SIG" "3.BB Via to Route Keepin" "0 MIL [DEFAULT]" "2062.58 MIL" "-2062.58 MIL" "DRC ERROR CLASS/L5-SIG" "[Shape] Route Keepin/All ((-2611.73 -1560.75) (2448.51 1842.01))" "[B/BVia] Dummy (VIA18D8A26-L3-L6) (-2910.0 -2782.0)" list(-2599.510000 -733.820000) nil)@@@list("sky_zheng" "2013/09/13 10:57:16" nil "RDD_704_PC" "g1t-oxygen.10")@@@list("andy_lien" "2013/09/13 12:15:07" nil "ANDY_LIEN-PC" "g1t-oxygen.10") | list("[Spacing] L5-SIG" "1.Shape to Route Keepin" "0 MIL [DEFAULT]" "0 MIL" "0.00 MIL" "DRC ERROR CLASS/L5-SIG" "[Shape] Route Keepin/All ((-2611.73 -1560.75) (2448.51 1842.01))" "[L5-Sig Shape] GND ((-2199.6 1385.1) (-2005.01 1752.87))" list(-2195.600000 1424.680000) nil)@@@list("sky_zheng" "2013/09/13 10:57:04" nil "RDD_704_PC" "g1t-oxygen.10")@@@list("andy_lien" "2013/09/13 12:15:06" nil "ANDY_LIEN-PC" "g1t-oxygen.10") | list("[Spacing] L5-SIG" "2.Shape to Route Keepin" "0 MIL [DEFAULT]" "0 MIL" "0.00 MIL" "DRC ERROR CLASS/L5-SIG" "[Shape] Route Keepin/All ((-2611.73 -1560.75) (2448.51 1842.01))" "[L5-Sig Shape] GND ((-2611.73 -1560.75) (2448.51 1842.01))" list(-13.300000 -778.660000) nil)@@@list("sky_zheng" "2013/09/13 10:57:05" nil "RDD_704_PC" "g1t-oxygen.10")@@@list("andy_lien" "2013/09/13 12:15:07" nil "ANDY_LIEN-PC" "g1t-oxygen.10") | list("[Spacing] L5-SIG" "37.Shape to Route Keepout" "0 MIL [DEFAULT]" "0 MIL" "0.00 MIL" "DRC ERROR CLASS/L5-SIG" "[Shape] Route Keepout/All ((190.63 -1315.47) (634.34 -438.7))" "[L5-Sig Shape] GND ((170.63 -1335.48) (654.34 -418.71))" list(190.630000 -495.210000) nil)@@@list("sky_zheng" "2013/09/13 10:57:02" nil "RDD_704_PC" "g1t-oxygen.10")@@@nil | list("[Spacing] L5-SIG" "38.Shape to Route Keepout" "0 MIL [DEFAULT]" "0 MIL" "0.00 MIL" "DRC ERROR CLASS/L5-SIG" "[Shape] Route Keepout/All ((184.14 -1363.31) (414.46 -390.87))" "[L5-Sig Shape] GND ((170.63 -1335.48) (654.34 -418.71))" list(390.830000 -418.710000) nil)@@@list("sky_zheng" "2013/09/13 10:57:03" nil "RDD_704_PC" "g1t-oxygen.10")@@@nil
